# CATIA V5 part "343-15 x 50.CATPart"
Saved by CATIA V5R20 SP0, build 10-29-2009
Part number: 343-15 x 50
Definition: NONE
Nomenclature: 343-15 x 50
Source: Unknown
Description: 343-15 x 50
Bounding box of the stored display mesh (mm): x 0 to 50, y -13 to 13, z -13 to 13
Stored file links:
  C:\Users\Utente\Desktop\IO LAVORO\3D X SITO CF\X SITO\343-348\343-15 x 50.CATPart
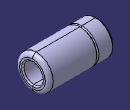
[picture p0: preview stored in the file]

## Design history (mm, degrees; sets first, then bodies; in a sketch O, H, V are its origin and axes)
Body1 "343-15 x 50" (main body)
  Solid1: solid without history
